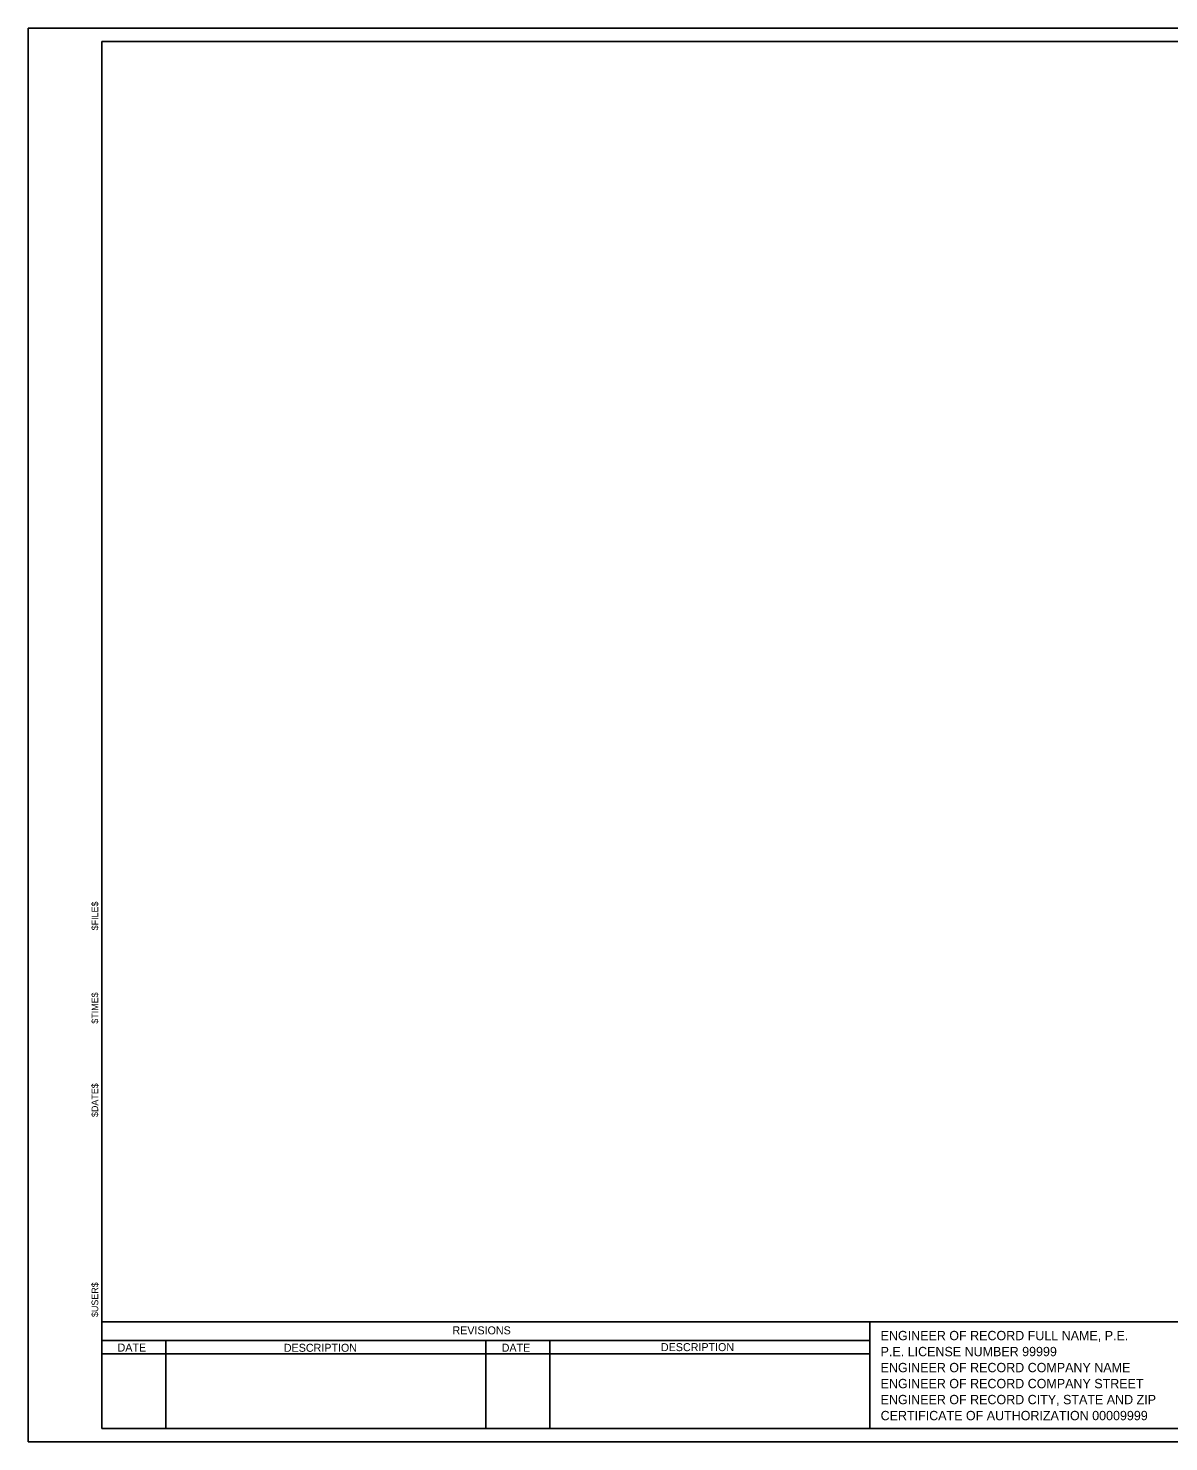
# Model space of a CAD drawing. Extents: x -765 to 885, y -614 to 446.
# Drawn here: x -765 to 90, y -614 to 446 of the extents above; entities that cross this region are included whole.
import ezdxf

# ---------------------------------------------------------------- set-up
doc = ezdxf.new("R2010")
doc.units = 0
for name, color, linetype in [('AdhocPoint_dp', 7, 'Continuous'), ('PlotBorder_dp', 7, 'Continuous'), ('SheetBorder_dp', 7, 'Continuous'), ('SheetLines_dp', 7, 'Continuous'), ('TextMinor', 7, 'Continuous'), ('TextMisc', 7, 'Continuous'), ('TextNotes', 7, 'Continuous')]:
    doc.layers.add(name, color=color, linetype=linetype)

msp = doc.modelspace()

# ---------------------------------------------------------------- linework, layer by layer
at = {"layer": 'AdhocPoint_dp'}
msp.add_line((-764.7, -613.8), (-764.7, -613.8), dxfattribs=at)
at = {"layer": 'PlotBorder_dp'}
msp.add_lwpolyline([(-764.7, -613.8), (885.3, -613.8), (885.3, 446.2), (-764.7, 446.2)], close=True, dxfattribs=at)
at = {"layer": 'SheetBorder_dp'}
for p, q in [((-709.7, 436.2), (-709.7, -603.8)), ((-709.7, 436.2), (830.3, 436.2)), ((-709.7, -523.8), (830.3, -523.8)), ((-709.7, -603.8), (830.3, -603.8))]:
    msp.add_line(p, q, dxfattribs=at)
at = {"layer": 'SheetLines_dp'}
for p, q in [((-133.7, -523.8), (-133.7, -603.8)), ((-709.7, -537.8), (-133.7, -537.8)), ((-661.7, -537.8), (-661.7, -603.8)), ((-421.7, -537.8), (-421.7, -603.8)), ((-373.7, -537.8), (-373.7, -603.8)), ((-709.7, -547.8), (-133.7, -547.8))]:
    msp.add_line(p, q, dxfattribs=at)

# ---------------------------------------------------------------- texts
at = {"layer": 'TextMinor'}
for s, p in [('$FILE$', (-712.3, -230.3)), ('$TIME$', (-712.3, -300.3)), ('$DATE$', (-712.3, -370.3)), ('$USER$', (-712.3, -520.3))]:
    msp.add_text(s, height=5, rotation=90, dxfattribs=at).set_placement(p)
at = {"layer": 'TextMisc'}
for s, rotation, p in [('REVISIONS', 360, (-446.7, -533.3)), ('DATE', 359.8693, (-697.8, -546.2)), ('DESCRIPTION', 0.0498, (-573.1, -546.4)), ('DATE', 359.8693, (-409.8, -546.3)), ('DESCRIPTION', 0.0498, (-290.4, -545.9))]:
    msp.add_text(s, height=6, rotation=rotation, dxfattribs=at).set_placement(p)
at = {"layer": 'TextNotes'}
for s, p in [('ENGINEER OF RECORD FULL NAME, P.E.    ', (-125.7, -537.7)), ('P.E. LICENSE NUMBER 99999', (-125.7, -549.7)), ('ENGINEER OF RECORD COMPANY NAME       ', (-125.7, -561.7)), ('ENGINEER OF RECORD COMPANY STREET     ', (-125.7, -573.7)), ('ENGINEER OF RECORD CITY, STATE AND ZIP', (-125.7, -585.7)), ('CERTIFICATE OF AUTHORIZATION 00009999', (-125.7, -597.7))]:
    msp.add_text(s, height=7, dxfattribs=at).set_placement(p)

doc.saveas('drawing.dxf')
